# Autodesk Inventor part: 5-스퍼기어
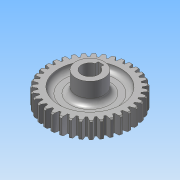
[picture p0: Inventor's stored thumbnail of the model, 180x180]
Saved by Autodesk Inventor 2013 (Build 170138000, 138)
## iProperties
Created: 2013-08
Part Number: 5-스퍼기어
Material: 강
Document SubType Name: Modeling
Designer: 한국산업디자인학원
Categories: <?xml version="1.0" encoding="UTF-16"?> <MemberInstance><Categories><FamilyTemplate><FamilyTemplateParameter ValueType="xs:double" Id="1" ObjectReferenceKey="da
Density: 1 g/cm^3
CustomPartVersion: 1
Author: 한국산업디자인학원
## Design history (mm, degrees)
sketch "Sketch1"
  geometry: C1 r 37 at (0, 0)
  constraints: 1 centre point
  dimensions: "d0" = 74 diameter of C1 (= da_da)
extrude "Extrusion1" new body sketch "Sketch1" distance "d1" = 15 (= da_b); taper "d2" = 0 deg
chamfer "모따기1" distance "d69" = 1; stored, may be unused: second distance "d70" = 2, angle "d71" = 45 deg
workplane "Work Plane2"
feature "피치 지름" dims "d4" = 10, "d5" = 0
workplane "Work Plane8"
workplane "Work Plane9"
feature "스퍼 기어" dims "da_b" = 15, "da_d" = 70, "da_aw" = 70, "da_da" = 74, "da_df" = 65, "da_dw" = 70, angle "da_beta" = 0 deg, "da_lefttooth" = 0, "da_righttooth" = 0
node "작업 평면11"
sketch "스케치3"
  geometry: C1 r 12.5 at (0, 0); 1 further point
  constraints: 1 centre point, 1 coincident
  dimensions: "d50" = 25 diameter of C1
extrude "돌출2" join sketch "스케치3" distance "d52" = 31; taper "d53" = 0 deg
sketch "스케치4"
  geometry: L1 (-2.5, 7.071)-(-2.5, 9.8); L2 (-2.5, 9.8)-(2.5, 9.8); L3 (2.5, 9.8)-(2.5, 7.071); C1 r 12.5 at (0, 0) reference; A1 r 7.5 centre (0, 0) between (-2.5, 7.071) and (2.5, 7.071)
  constraints: 6 end point, 2 parallel, 2 point on circle, 1 centre point, 1 coincident, 1 perpendicular, 1 vertical
  dimensions: "d54" = 15 diameter of A1; "d56" = 5 distance of L1.end L2.end; "d57" = 17.3 dimension on A1 L2
extrude "돌출3" cut sketch "스케치4" stored distance "d58" = 31; taper "d59" = 0 deg
sketch "스케치8"
  geometry: C1 r 12.5 at (0, 0) reference; C2 r 27.5 at (0, 0); C3 r 12.5 at (0, 0)
  constraints: 2 centre point, 2 coincident, 1 concentric
  dimensions: "d74" = 55 diameter of C2
extrude "돌출6" cut sketch "스케치8" distance "d76" = 5; taper "d77" = 0 deg
sketch "스케치9"
  geometry: C1 r 12.5 at (0, 0) reference; C2 r 27.5 at (0, 0); C3 r 12.5 at (0, 0); A1 r 32.5 centre (0, 0) between (9.347, 31.127) and (7.941, 31.515) reference
  constraints: 2 centre point, 2 coincident, 1 concentric
  dimensions: "d78" = 55 diameter of C2
extrude "돌출7" cut sketch "스케치9" distance "d80" = 5; taper "d81" = 0 deg
fillet "모깎기1" dims "d68" = 5
body "Solid1"
sketch "Sketch2"
  geometry: C1 r 37 at (0, 0) reference; C2 r 35 at (0, 0)
  constraints: 1 centre point, 1 coincident
  dimensions: "d3" = 70 diameter of C2 (= da_dw)
body "Srf1"
other parameters: "d17" = 0, "d34" = 0.8976 (computed from da_z), "d39" = 0, "d41" = 0, "d47" = 0, "d48" = 0, "d49" = -3
